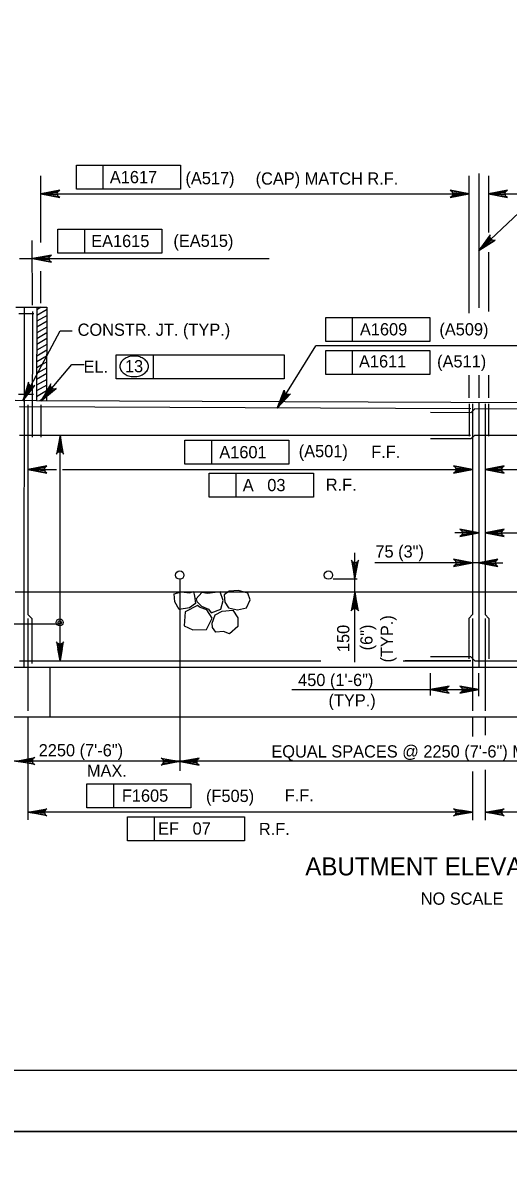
# Model space of a CAD drawing. Extents: x 634540 to 640306, y 296059 to 300275.
# Drawn here: x 638645.1 to 638764.2, y 296646 to 296925.5 of the extents above; entities that cross this region are included whole.
import ezdxf

# ---------------------------------------------------------------- set-up
doc = ezdxf.new("R2010")
doc.units = 0
for name, color, linetype in [('10', 7, 'Continuous'), ('2', 7, 'Continuous'), ('3', 7, 'Continuous'), ('4', 7, 'Continuous'), ('5', 7, 'Continuous'), ('PLT-BNDY', 7, 'Continuous')]:
    doc.layers.add(name, color=color, linetype=linetype)

# ---------------------------------------------------------------- blocks, each defined once
blk = doc.blocks.new('ROCK')
at = {"layer": '4'}
for points in [[(2.36725, 1.088), (2.2065, 0.82625), (2.378625, 0.506625), (2.66975, 0.3095), (3.128875, 0.403375), (3.48475, 0.6775), (3.4915, 1.123375), (3.25625, 1.36725), (2.783625, 1.308375)], [(1.10175, -0.02725), (1.4015, -0.159125), (1.78825, -0.148875), (1.980875, -0.266), (2.343375, 0.09475), (2.27875, 0.5505), (1.969375, 0.883), (1.4225, 0.553625), (1.152875, 0.479), (1.0105, 0.082)], [(0.74675, 0.359875), (0.882, 0.16), (1.072875, -0.144), (0.892, -0.457375), (0.448125, -0.758625), (0.1, -0.49325), (-0.095, -0.146375), (0.202875, 0.1025), (0.579125, 0.219875)], [(2.231375, -0.71725), (2.2025, -0.266375), (2.45475, 0.037125), (2.9085, 0.28875), (3.2995, 0.047625), (3.46875, -0.344), (3.231625, -0.855), (2.92, -0.860375), (2.5765, -1.054625), (2.340375, -0.904375)], [(1.2085, -0.192875), (0.778375, -0.737625), (1.008375, -1.391375), (1.48725, -1.396875), (2.09825, -1.106625), (2.133375, -0.486375), (1.723125, -0.203375), (1.37425, -0.239875)]]:
    blk.add_lwpolyline(points, close=True, dxfattribs=at)

msp = doc.modelspace()

# ---------------------------------------------------------------- linework, layer by layer
at = {"layer": '10'}
for p, q in [((638757, 296888.54), (638757, 296855.58)), ((638643.36, 296855.72), (638651, 296855.72)), ((638645.45, 296855.72), (638645.38, 296767.44)), ((638648.52, 296855.72), (638648.46, 296832.77)), ((638651.04, 296855.13), (638648.56, 296853.7)), ((638649.61, 296855.72), (638648.57, 296855.12)), ((638651, 296855.72), (638650.93, 296832.76)), ((638651.03, 296852.28), (638648.55, 296850.85)), ((638651.04, 296853.71), (638648.56, 296852.28)), ((638651.02, 296850.86), (638648.54, 296849.43)), ((638651.02, 296849.43), (638648.54, 296848)), ((638651, 296846.58), (638648.52, 296845.15)), ((638651.01, 296848.01), (638648.53, 296846.58)), ((638650.99, 296845.16), (638648.51, 296843.73)), ((638650.92, 296843.7), (638648.51, 296842.3)), ((638650.99, 296843.73), (638650.92, 296843.7)), ((638649.83, 296841.65), (638648.5, 296840.88)), ((638650.97, 296840.88), (638648.74, 296839.59)), ((638650.98, 296842.31), (638649.83, 296841.65)), ((638650.96, 296838.03), (638648.48, 296836.6)), ((638648.74, 296839.59), (638648.49, 296839.45)), ((638650.97, 296839.46), (638648.49, 296838.03)), ((638757, 296839.04), (638757, 296833.51)), ((638650.94, 296835.18), (638648.46, 296833.75)), ((638650.95, 296836.61), (638648.47, 296835.18)), ((638648.46, 296832.77), (638643.24, 296832.8)), ((638865.51, 296831.85), (638648.46, 296832.77)), ((638650.94, 296833.76), (638649.23, 296832.77)), ((638757, 296832.16), (638757, 296767.44)), ((638643.24, 296785.9), (638662.66, 296785.9)), ((638662.66, 296785.9), (638872.48, 296785.9)), ((638573.46, 296767.44), (638721.59, 296767.44)), ((638651.73, 296767.44), (638651.73, 296755.14)), ((638721.59, 296767.44), (638775.05, 296767.44)), ((638954.7, 296755.14), (638573.46, 296755.14))]:
    msp.add_line(p, q, dxfattribs=at)
at = {"layer": '2'}
msp.add_line((639261.46, 296668.46), (638475.46, 296668.46), dxfattribs=at)
at = {"layer": '3'}
for p, q in [((638658.26, 296890.56), (638683.8, 296890.56)), ((638658.26, 296884.66), (638658.26, 296890.56)), ((638664.85, 296884.66), (638664.85, 296890.56)), ((638683.8, 296890.56), (638683.8, 296884.66)), ((638649.48, 296871.62), (638649.48, 296887.97)), ((638754.62, 296854.28), (638754.62, 296887.99)), ((638759.34, 296887.99), (638759.34, 296874.03)), ((638649.48, 296883.54), (638754.62, 296883.54)), ((638683.8, 296884.66), (638658.26, 296884.66)), ((638759.34, 296883.54), (638864.49, 296883.54)), ((638757, 296869.61), (638766.86, 296878.99)), ((638653.68, 296874.9), (638679.22, 296874.9)), ((638653.68, 296869), (638653.68, 296874.9)), ((638660.28, 296869), (638660.28, 296874.9)), ((638679.22, 296874.9), (638679.22, 296869)), ((638647.5, 296856.23), (638647.43, 296872.09)), ((638679.22, 296869), (638653.68, 296869)), ((638759.34, 296869.27), (638759.34, 296854.71)), ((638644.27, 296867.66), (638647.43, 296867.66)), ((638647.45, 296867.66), (638705.57, 296867.66)), ((638650.39, 296867.66), (638653.34, 296867.66)), ((638649.48, 296856.76), (638649.48, 296864.6)), ((638719.4, 296853.23), (638744.94, 296853.23)), ((638719.4, 296847.32), (638719.4, 296853.23)), ((638725.99, 296847.32), (638725.99, 296853.23)), ((638744.94, 296853.23), (638744.94, 296847.32)), ((638645.12, 296832.79), (638654.24, 296849.92)), ((638654.24, 296849.92), (638657.19, 296849.92)), ((638707.53, 296830.99), (638716.99, 296846.23)), ((638782.28, 296846.23), (638716.99, 296846.23)), ((638744.94, 296847.32), (638719.4, 296847.32)), ((638668.02, 296844.06), (638677.19, 296844.06)), ((638668.02, 296838.16), (638668.02, 296844.06)), ((638677.19, 296838.16), (638677.19, 296844.06)), ((638677.19, 296844.06), (638709.23, 296844.06)), ((638709.23, 296844.06), (638709.23, 296838.16)), ((638719.4, 296839.24), (638719.4, 296845.14)), ((638719.4, 296845.14), (638744.94, 296845.14)), ((638725.99, 296839.24), (638725.99, 296845.14)), ((638744.94, 296845.14), (638744.94, 296839.24)), ((638649.6, 296832.77), (638657.16, 296841.7)), ((638657.16, 296841.7), (638660.11, 296841.7)), ((638709.23, 296838.16), (638668.02, 296838.16)), ((638744.94, 296839.24), (638719.4, 296839.24)), ((638754.62, 296833.5), (638754.62, 296839.04)), ((638759.34, 296839.04), (638759.34, 296833.5)), ((638654.22, 296797.17), (638654.22, 296824.35)), ((638684.86, 296823.08), (638710.4, 296823.08)), ((638684.86, 296817.18), (638684.86, 296823.08)), ((638691.45, 296817.18), (638691.45, 296823.08)), ((638710.4, 296823.08), (638710.4, 296817.18)), ((638646.36, 296815.92), (638653.32, 296815.92)), ((638654.83, 296815.92), (638755.46, 296815.92)), ((638710.4, 296817.18), (638684.86, 296817.18)), ((638758.53, 296815.92), (638858.1, 296815.92)), ((638690.85, 296809.1), (638690.85, 296815)), ((638690.85, 296815), (638716.39, 296815)), ((638697.45, 296809.1), (638697.45, 296815)), ((638716.39, 296815), (638716.39, 296809.1)), ((638716.39, 296809.1), (638690.85, 296809.1)), ((638757, 296800.37), (638751.09, 296800.37)), ((638758.53, 296800.37), (638785.23, 296800.37)), ((638654.22, 296768.98), (638654.22, 296797.17)), ((638726.56, 296768.65), (638726.56, 296795.45)), ((638749.55, 296793.02), (638731.43, 296793.02)), ((638755.46, 296793.02), (638749.55, 296793.02)), ((638757, 296793.02), (638755.46, 296793.02)), ((638757, 296793.02), (638762.9, 296793.02)), ((638727.16, 296788.98), (638721.2, 296788.98)), ((638579.54, 296778.04), (638654.22, 296778.04)), ((638745.08, 296760.47), (638745.08, 296765.98)), ((638757, 296760.33), (638757, 296765.98)), ((638711.06, 296761.9), (638757, 296761.9)), ((638646.36, 296755.14), (638646.36, 296729.99)), ((638755.46, 296755.14), (638755.46, 296750.42)), ((638758.53, 296755.14), (638758.53, 296750.77)), ((638875.79, 296744.38), (638589.73, 296744.38)), ((638755.46, 296741.81), (638755.46, 296729.91)), ((638755.46, 296741.38), (638755.46, 296740.36)), ((638758.53, 296742.24), (638758.53, 296729.91)), ((638758.53, 296742.07), (638758.53, 296740.36)), ((638660.8, 296738.81), (638686.34, 296738.81)), ((638660.8, 296732.91), (638660.8, 296738.81)), ((638667.4, 296732.91), (638667.4, 296738.81)), ((638686.34, 296738.81), (638686.34, 296732.91)), ((638755.46, 296731.82), (638646.36, 296731.82)), ((638686.34, 296732.91), (638660.8, 296732.91)), ((638872.53, 296731.82), (638758.53, 296731.82)), ((638670.79, 296724.83), (638670.79, 296730.73)), ((638670.79, 296730.73), (638699.45, 296730.73)), ((638677.38, 296724.83), (638677.38, 296730.73)), ((638699.45, 296730.73), (638699.45, 296724.83)), ((638699.45, 296724.83), (638670.79, 296724.83))]:
    msp.add_line(p, q, dxfattribs=at)
for points in [[(638649.48, 296883.54), (638654.14, 296882.67), (638653.78, 296882.92), (638653.59, 296883.23), (638653.54, 296883.54), (638653.59, 296883.86), (638653.78, 296884.17), (638654.14, 296884.42), (638649.48, 296883.54), (638653.78, 296884.17), (638653.59, 296883.86), (638649.48, 296883.54), (638653.54, 296883.54), (638653.59, 296883.23), (638649.48, 296883.54), (638653.78, 296882.92)], [(638754.62, 296883.54), (638749.96, 296884.42), (638750.32, 296884.17), (638750.5, 296883.86), (638750.56, 296883.54), (638750.5, 296883.23), (638750.32, 296882.92), (638749.96, 296882.67), (638754.62, 296883.54), (638750.32, 296882.92), (638750.5, 296883.23), (638754.62, 296883.54), (638750.56, 296883.54), (638750.5, 296883.86), (638754.62, 296883.54), (638750.32, 296884.17)], [(638759.34, 296883.54), (638764, 296882.67), (638763.64, 296882.92), (638763.45, 296883.23), (638763.4, 296883.54), (638763.45, 296883.86), (638763.64, 296884.17), (638764, 296884.42), (638759.34, 296883.54), (638763.64, 296884.17), (638763.45, 296883.86), (638759.34, 296883.54), (638763.4, 296883.54), (638763.45, 296883.23), (638759.34, 296883.54), (638763.64, 296882.92)], [(638757, 296869.61), (638760.97, 296872.19), (638760.54, 296872.12), (638760.19, 296872.22), (638759.94, 296872.41), (638759.76, 296872.67), (638759.68, 296873.02), (638759.77, 296873.45), (638757, 296869.61), (638759.68, 296873.02), (638759.76, 296872.67), (638757, 296869.61), (638759.94, 296872.41), (638760.19, 296872.22), (638757, 296869.61), (638760.54, 296872.12)], [(638647.45, 296867.66), (638652.11, 296866.78), (638651.76, 296867.03), (638651.57, 296867.34), (638651.52, 296867.66), (638651.57, 296867.97), (638651.76, 296868.28), (638652.11, 296868.53), (638647.45, 296867.66), (638651.76, 296868.28), (638651.57, 296867.97), (638647.45, 296867.66), (638651.52, 296867.66), (638651.57, 296867.34), (638647.45, 296867.66), (638651.76, 296867.03)], [(638645.12, 296832.79), (638648.08, 296836.49), (638647.69, 296836.29), (638647.33, 296836.28), (638647.03, 296836.38), (638646.77, 296836.57), (638646.59, 296836.88), (638646.53, 296837.31), (638645.12, 296832.79), (638646.59, 296836.88), (638646.77, 296836.57), (638645.12, 296832.79), (638647.03, 296836.38), (638647.33, 296836.28), (638645.12, 296832.79), (638647.69, 296836.29)], [(638649.6, 296832.77), (638653.28, 296835.76), (638652.86, 296835.65), (638652.5, 296835.71), (638652.23, 296835.87), (638652.02, 296836.11), (638651.9, 296836.46), (638651.95, 296836.89), (638649.6, 296832.77), (638651.9, 296836.46), (638652.02, 296836.11), (638649.6, 296832.77), (638652.23, 296835.87), (638652.5, 296835.71), (638649.6, 296832.77), (638652.86, 296835.65)], [(638707.53, 296830.99), (638709.25, 296835.41), (638709.27, 296834.97), (638709.44, 296834.65), (638709.67, 296834.44), (638709.97, 296834.32), (638710.33, 296834.31), (638710.73, 296834.49), (638707.53, 296830.99), (638710.33, 296834.31), (638709.97, 296834.32), (638707.53, 296830.99), (638709.67, 296834.44), (638709.44, 296834.65), (638707.53, 296830.99), (638709.27, 296834.97)], [(638654.22, 296824.35), (638653.34, 296819.69), (638653.59, 296820.05), (638653.9, 296820.23), (638654.22, 296820.28), (638654.53, 296820.23), (638654.84, 296820.05), (638655.09, 296819.69), (638654.22, 296824.35), (638654.84, 296820.05), (638654.53, 296820.23), (638654.22, 296824.35), (638654.22, 296820.28), (638653.9, 296820.23), (638654.22, 296824.35), (638653.59, 296820.05)], [(638646.36, 296815.92), (638651.02, 296815.04), (638650.66, 296815.29), (638650.48, 296815.6), (638650.42, 296815.92), (638650.48, 296816.23), (638650.66, 296816.54), (638651.02, 296816.79), (638646.36, 296815.92), (638650.66, 296816.54), (638650.48, 296816.23), (638646.36, 296815.92), (638650.42, 296815.92), (638650.48, 296815.6), (638646.36, 296815.92), (638650.66, 296815.29)], [(638755.46, 296815.92), (638750.8, 296816.79), (638751.16, 296816.54), (638751.34, 296816.23), (638751.4, 296815.92), (638751.34, 296815.6), (638751.16, 296815.29), (638750.8, 296815.04), (638755.46, 296815.92), (638751.16, 296815.29), (638751.34, 296815.6), (638755.46, 296815.92), (638751.4, 296815.92), (638751.34, 296816.23), (638755.46, 296815.92), (638751.16, 296816.54)], [(638758.53, 296815.92), (638763.19, 296815.04), (638762.84, 296815.29), (638762.65, 296815.6), (638762.6, 296815.92), (638762.65, 296816.23), (638762.84, 296816.54), (638763.19, 296816.79), (638758.53, 296815.92), (638762.84, 296816.54), (638762.65, 296816.23), (638758.53, 296815.92), (638762.6, 296815.92), (638762.65, 296815.6), (638758.53, 296815.92), (638762.84, 296815.29)], [(638757, 296800.37), (638752.34, 296801.24), (638752.69, 296800.99), (638752.88, 296800.68), (638752.93, 296800.37), (638752.88, 296800.06), (638752.69, 296799.74), (638752.34, 296799.49), (638757, 296800.37), (638752.69, 296799.74), (638752.88, 296800.06), (638757, 296800.37), (638752.93, 296800.37), (638752.88, 296800.68), (638757, 296800.37), (638752.69, 296800.99)], [(638758.53, 296800.37), (638763.19, 296799.5), (638762.84, 296799.74), (638762.65, 296800.06), (638762.6, 296800.37), (638762.65, 296800.68), (638762.84, 296800.99), (638763.19, 296801.24), (638758.53, 296800.37), (638762.84, 296800.99), (638762.65, 296800.68), (638758.53, 296800.37), (638762.6, 296800.37), (638762.65, 296800.06), (638758.53, 296800.37), (638762.84, 296799.74)], [(638726.58, 296788.97), (638727.45, 296793.64), (638727.2, 296793.28), (638726.89, 296793.09), (638726.58, 296793.04), (638726.27, 296793.09), (638725.95, 296793.28), (638725.71, 296793.64), (638726.58, 296788.97), (638725.95, 296793.28), (638726.27, 296793.09), (638726.58, 296788.97), (638726.58, 296793.04), (638726.89, 296793.09), (638726.58, 296788.97), (638727.2, 296793.28)], [(638755.46, 296793.02), (638750.8, 296793.9), (638751.16, 296793.65), (638751.34, 296793.34), (638751.4, 296793.02), (638751.34, 296792.71), (638751.16, 296792.4), (638750.8, 296792.15), (638755.46, 296793.02), (638751.16, 296792.4), (638751.34, 296792.71), (638755.46, 296793.02), (638751.4, 296793.02), (638751.34, 296793.34), (638755.46, 296793.02), (638751.16, 296793.65)], [(638757, 296793.02), (638761.66, 296792.15), (638761.3, 296792.4), (638761.11, 296792.71), (638761.06, 296793.02), (638761.11, 296793.34), (638761.3, 296793.65), (638761.66, 296793.9), (638757, 296793.02), (638761.3, 296793.65), (638761.11, 296793.34), (638757, 296793.02), (638761.06, 296793.02), (638761.11, 296792.71), (638757, 296793.02), (638761.3, 296792.4)], [(638726.56, 296785.9), (638725.69, 296781.24), (638725.93, 296781.6), (638726.25, 296781.78), (638726.56, 296781.84), (638726.87, 296781.78), (638727.18, 296781.6), (638727.43, 296781.24), (638726.56, 296785.9), (638727.18, 296781.6), (638726.87, 296781.78), (638726.56, 296785.9), (638726.56, 296781.84), (638726.25, 296781.78), (638726.56, 296785.9), (638725.93, 296781.6)], [(638654.22, 296768.98), (638655.09, 296773.64), (638654.84, 296773.28), (638654.53, 296773.1), (638654.22, 296773.04), (638653.9, 296773.1), (638653.59, 296773.28), (638653.34, 296773.64), (638654.22, 296768.98), (638653.59, 296773.28), (638653.9, 296773.1), (638654.22, 296768.98), (638654.22, 296773.04), (638654.53, 296773.1), (638654.22, 296768.98), (638654.84, 296773.28)], [(638745.02, 296761.9), (638749.68, 296761.02), (638749.32, 296761.27), (638749.13, 296761.58), (638749.08, 296761.9), (638749.13, 296762.21), (638749.32, 296762.52), (638749.68, 296762.77), (638745.02, 296761.9), (638749.32, 296762.52), (638749.13, 296762.21), (638745.02, 296761.9), (638749.08, 296761.9), (638749.13, 296761.58), (638745.02, 296761.9), (638749.32, 296761.27)], [(638757, 296761.9), (638752.34, 296762.77), (638752.69, 296762.52), (638752.88, 296762.21), (638752.93, 296761.9), (638752.88, 296761.58), (638752.69, 296761.27), (638752.34, 296761.02), (638757, 296761.9), (638752.69, 296761.27), (638752.88, 296761.58), (638757, 296761.9), (638752.93, 296761.9), (638752.88, 296762.21), (638757, 296761.9), (638752.69, 296762.52)], [(638646.36, 296731.82), (638651.02, 296732.69), (638650.66, 296732.44), (638650.48, 296732.13), (638650.42, 296731.82), (638650.48, 296731.5), (638650.66, 296731.19), (638651.02, 296730.94), (638646.36, 296731.82), (638650.66, 296731.19), (638650.48, 296731.5), (638646.36, 296731.82), (638650.42, 296731.82), (638650.48, 296732.13), (638646.36, 296731.82), (638650.66, 296732.44)], [(638755.46, 296731.82), (638750.8, 296730.94), (638751.16, 296731.19), (638751.34, 296731.5), (638751.4, 296731.82), (638751.34, 296732.13), (638751.16, 296732.44), (638750.8, 296732.69), (638755.46, 296731.82), (638751.16, 296732.44), (638751.34, 296732.13), (638755.46, 296731.82), (638751.4, 296731.82), (638751.34, 296731.5), (638755.46, 296731.82), (638751.16, 296731.19)], [(638758.53, 296731.82), (638763.19, 296732.69), (638762.84, 296732.44), (638762.65, 296732.13), (638762.6, 296731.82), (638762.65, 296731.5), (638762.84, 296731.19), (638763.19, 296730.94), (638758.53, 296731.82), (638762.84, 296731.19), (638762.65, 296731.5), (638758.53, 296731.82), (638762.6, 296731.82), (638762.65, 296732.13), (638758.53, 296731.82), (638762.84, 296732.44)]]:
    msp.add_lwpolyline(points, dxfattribs=at)
for points in [[(638759.48, 296871.27), (638758.81, 296871.99), (638757, 296869.61)], [(638650.39, 296868.15), (638650.39, 296867.16), (638647.43, 296867.66)], [(638646.94, 296835.16), (638646.07, 296835.63), (638645.12, 296832.79)], [(638651.89, 296834.71), (638651.13, 296835.34), (638649.6, 296832.77)], [(638653.72, 296821.4), (638654.71, 296821.4), (638654.22, 296824.35)], [(638752.5, 296816.41), (638752.5, 296815.42), (638755.46, 296815.92)], [(638761.49, 296816.41), (638761.49, 296815.42), (638758.53, 296815.92)], [(638754.04, 296800.86), (638754.04, 296799.88), (638757, 296800.37)], [(638761.49, 296800.86), (638761.49, 296799.88), (638758.53, 296800.37)], [(638752.5, 296793.51), (638752.5, 296792.53), (638755.46, 296793.02)], [(638759.95, 296793.51), (638759.95, 296792.53), (638757, 296793.02)], [(638726.07, 296782.95), (638727.05, 296782.95), (638726.56, 296785.9)], [(638653.72, 296771.93), (638654.71, 296771.93), (638654.22, 296768.98)], [(638752.51, 296732.31), (638752.51, 296731.32), (638755.46, 296731.82)], [(638761.49, 296732.31), (638761.49, 296731.32), (638758.53, 296731.82)]]:
    msp.add_lwpolyline(points, close=True, dxfattribs=at)
for centre, radius in [((638683.59, 296790), 1.03), ((638720.08, 296790), 1.03), ((638654.15, 296778.41), 0.833), ((638654.15, 296778.41), 0.417)]:
    msp.add_circle(centre, radius, dxfattribs=at)
for centre, radius, start, end in [((638672.06, 296840.02), 3.66, 106.5358, 125.6316), ((638672.4, 296838.86), 4.87, 90, 106.5358), ((638672.4, 296838.86), 4.87, 73.4642, 90), ((638672.74, 296840.02), 3.66, 54.3684, 73.4642), ((638670.72, 296841.22), 1.83, 149.9767, 180), ((638670.72, 296841.22), 1.83, 180, 210.0233), ((638671.53, 296840.75), 2.76, 125.6316, 149.9767), ((638673.27, 296840.75), 2.76, 30.0233, 54.3684), ((638674.08, 296841.22), 1.83, 0, 30.0233), ((638674.08, 296841.22), 1.83, 329.9767, 0), ((638671.53, 296841.69), 2.76, 210.0233, 234.3684), ((638672.06, 296842.42), 3.66, 234.3684, 253.4642), ((638672.4, 296843.58), 4.87, 253.4642, 270), ((638672.4, 296843.58), 4.87, 270, 286.5358), ((638672.74, 296842.42), 3.66, 286.5358, 305.6316), ((638673.27, 296841.69), 2.76, 305.6316, 329.9767)]:
    msp.add_arc(centre, radius, start, end, dxfattribs=at)
at = {"layer": '4'}
for points in [[(638643.36, 296744.38), (638648.02, 296745.25), (638647.66, 296745.01), (638647.47, 296744.69), (638647.42, 296744.38), (638647.47, 296744.07), (638647.66, 296743.76), (638648.02, 296743.51), (638643.36, 296744.38), (638647.66, 296743.76), (638647.47, 296744.07), (638643.36, 296744.38), (638647.42, 296744.38), (638647.47, 296744.69), (638643.36, 296744.38), (638647.66, 296745.01)], [(638683.71, 296744.25), (638679.05, 296743.37), (638679.4, 296743.62), (638679.59, 296743.93), (638679.64, 296744.25), (638679.59, 296744.56), (638679.4, 296744.87), (638679.05, 296745.12), (638683.71, 296744.25), (638679.4, 296744.87), (638679.59, 296744.56), (638683.71, 296744.25), (638679.64, 296744.25), (638679.59, 296743.93), (638683.71, 296744.25), (638679.4, 296743.62)], [(638683.71, 296744.25), (638688.37, 296743.37), (638688.01, 296743.62), (638687.82, 296743.93), (638687.77, 296744.25), (638687.82, 296744.56), (638688.01, 296744.87), (638688.37, 296745.12), (638683.71, 296744.25), (638688.01, 296744.87), (638687.82, 296744.56), (638683.71, 296744.25), (638687.77, 296744.25), (638687.82, 296743.93), (638683.71, 296744.25), (638688.01, 296743.62)]]:
    msp.add_lwpolyline(points, dxfattribs=at)
at = {"layer": '5'}
for p, q in [((638647.5, 296854.7), (638647.43, 296823.83)), ((638644.08, 296854.18), (638647.76, 296854.18)), ((638647.69, 296834.32), (638644.01, 296834.32)), ((638755.03, 296830.79), (638644.27, 296831.26)), ((638646.36, 296831.77), (638646.36, 296780.31)), ((638649.48, 296831.77), (638649.49, 296823.84)), ((638755.02, 296829.85), (638745.08, 296829.89)), ((638754.62, 296832), (638754.64, 296824.07)), ((638755.96, 296830.78), (638755.02, 296829.85)), ((638755.46, 296831.99), (638755.46, 296780.31)), ((638874.65, 296830.27), (638755.96, 296830.78)), ((638758.53, 296831.99), (638758.53, 296780.31)), ((638759.34, 296832), (638759.35, 296824.07)), ((638644.27, 296824.35), (638754.92, 296824.35)), ((638755.97, 296824.35), (638755.04, 296823.41)), ((638755.97, 296824.35), (638874.65, 296824.35)), ((638755.04, 296823.41), (638745.1, 296823.41)), ((638683.59, 296788.97), (638683.59, 296742)), ((638646.36, 296780.31), (638647.3, 296779.38)), ((638646.36, 296779.38), (638646.36, 296756.68)), ((638647.3, 296779.38), (638647.3, 296768.33)), ((638755.46, 296780.31), (638754.52, 296779.38)), ((638754.52, 296779.38), (638754.52, 296769.44)), ((638755.46, 296779.38), (638755.46, 296756.68)), ((638758.53, 296780.31), (638759.47, 296779.38)), ((638758.53, 296779.38), (638758.53, 296756.68)), ((638759.47, 296779.38), (638759.47, 296769.44)), ((638644.27, 296768.98), (638718.23, 296768.98)), ((638738.38, 296768.98), (638754.92, 296768.98)), ((638755.04, 296768.98), (638738.94, 296768.98)), ((638755.04, 296769.92), (638745.1, 296769.92)), ((638755.97, 296768.98), (638755.04, 296769.92)), ((638755.97, 296768.98), (638774.51, 296768.98))]:
    msp.add_line(p, q, dxfattribs=at)
at = {"layer": 'PLT-BNDY'}
for points in [[(638435.46, 297247.46), (639276.46, 297247.46), (639276.46, 296653.46), (638435.46, 296653.46)], [(638435.46, 296653.46), (639276.46, 296653.46), (639276.46, 296059.46), (638435.46, 296059.46)]]:
    msp.add_lwpolyline(points, close=True, dxfattribs=at)

# ---------------------------------------------------------------- block references
at = {"layer": '3', "xscale": 4.921475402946, "yscale": 4.921475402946, "rotation": -23.78336161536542}
msp.add_blockref('ROCK', (638682.91, 296785.84), dxfattribs=at)

# ---------------------------------------------------------------- texts
at = {"layer": '3'}
for s, height, p in [('A1617', 3, (638666.45, 296886.15)), ('(A517)', 3, (638685, 296885.89)), ('(CAP) MATCH R.F.', 3.0001, (638702.22, 296885.8)), ('EA1615', 3, (638661.87, 296870.48)), ('(EA515)', 3, (638682.04, 296870.53)), ('CONSTR. JT. (TYP.)', 3.0001, (638658.54, 296848.71)), ('A1609', 3, (638727.81, 296848.81)), ('(A509)', 3, (638747.3, 296848.81)), ('A1611', 3, (638727.58, 296840.95)), ('(A511)', 3, (638746.74, 296840.95)), ('EL.', 3, (638660, 296839.65)), ('13', 3, (638670.15, 296839.76)), ('A1601', 3, (638693.31, 296818.67)), ('(A501)', 3, (638712.79, 296818.92)), ('F.F.', 3, (638730.58, 296818.77)), ('A   03', 3, (638699.06, 296810.59)), ('R.F.', 3, (638719.43, 296810.68)), ('75 (3")', 3, (638731.6, 296794.3)), ('450 (1\'-6")', 3.0001, (638712.64, 296762.78)), ('(TYP.)', 3, (638720.09, 296757.78)), ('2250 (7\'-6")', 3.0001, (638648.99, 296745.53)), ('EQUAL SPACES @ 2250 (7\'-6") MAX.', 3.0001, (638706.07, 296745.25)), ('MAX.', 3, (638660.82, 296740.53)), ('F1605', 3, (638669.4, 296734.4)), ('(F505)', 3, (638690.04, 296734.33)), ('F.F.', 3, (638709.36, 296734.48)), ('EF   07', 3, (638678.28, 296726.32)), ('R.F.', 3, (638703.02, 296726.22)), ('ABUTMENT ELEVATION', 4.4294, (638714.39, 296716.32)), ('NO SCALE', 3, (638742.73, 296709.13))]:
    msp.add_text(s, height=height, dxfattribs=at).set_placement(p)
for s, p in [('(TYP.)', (638735.91, 296768.56)), ('150', (638725.21, 296771.11)), ('(6")', (638730.9, 296771.53))]:
    msp.add_text(s, height=3, rotation=90, dxfattribs=at).set_placement(p)

doc.saveas('drawing.dxf')
